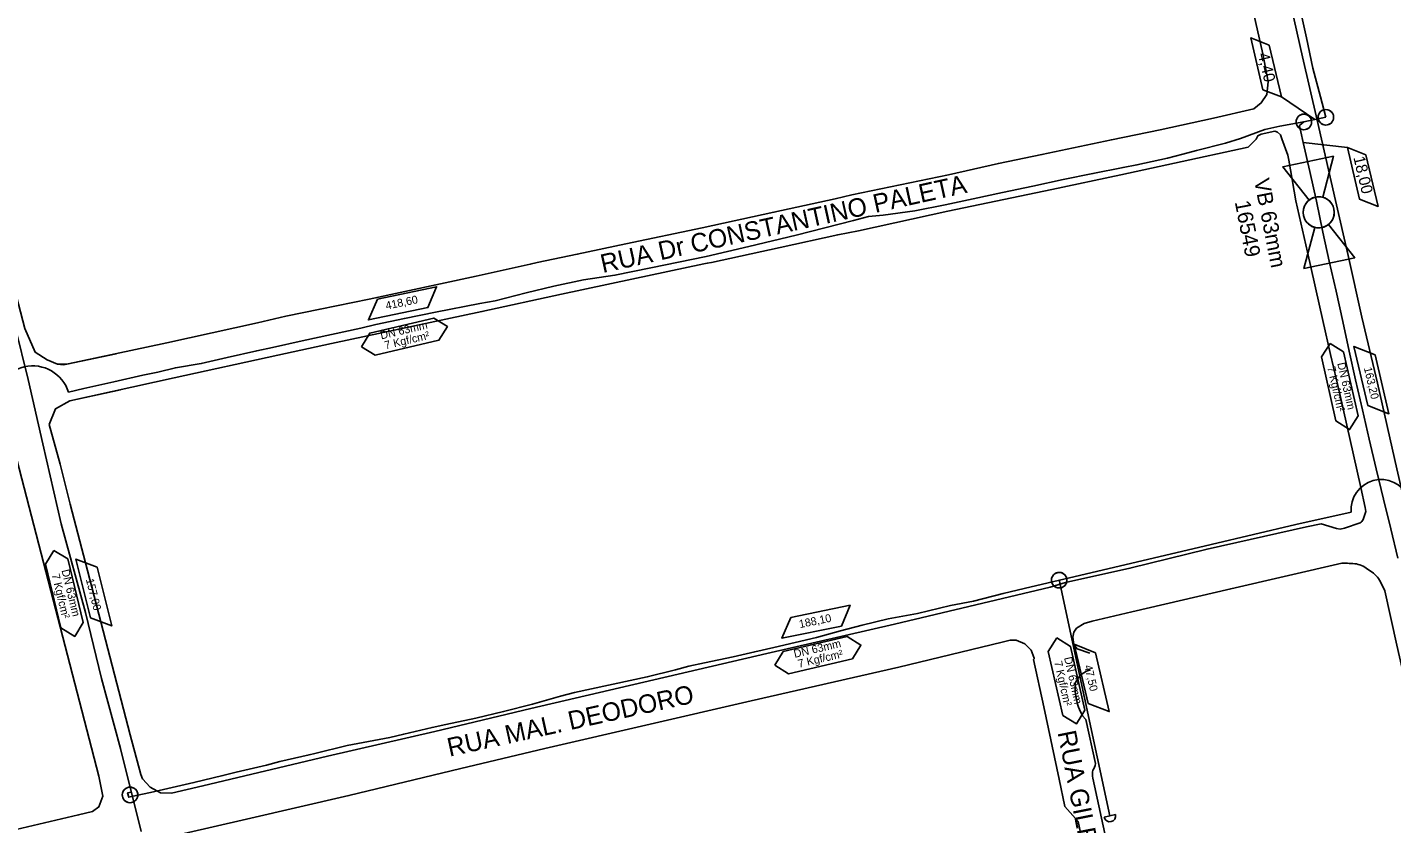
# Model space of a CAD drawing. Extents: x 656692 to 673945, y 7585994 to 7599066.
# Drawn here: x 669316 to 669847, y 7594083 to 7594394 of the extents above; entities that cross this region are included whole.
import ezdxf

# ---------------------------------------------------------------- set-up
doc = ezdxf.new("R2010")
doc.units = 0
for name, color, linetype in [('LOGRADOURO', 7, 'Continuous'), ('LOGRADOURO_TEXTO', 7, 'Continuous'), ('SIMBOLO', 7, 'Continuous'), ('TEXTO', 7, 'Continuous'), ('TUBO_PEAD_GN_63', 7, 'Continuous'), ('VALVULA_PEAD_63', 7, 'Continuous')]:
    doc.layers.add(name, color=color, linetype=linetype)

# ---------------------------------------------------------------- blocks, each defined once
blk = doc.blocks.new('VALVULA_PEAD_DN_16')
at = {"layer": 'VALVULA_PEAD_63'}
for points in [[(-0.0374, 0.0187), (-0.1395, 0.0698), (-0.1395, -0.0698), (-0.0374, -0.0187)], [(-0.0374, -0.0187), (-0.1395, -0.0698), (-0.1395, 0.0698), (-0.0374, 0.0187)], [(0.0374, -0.0187), (0.1395, -0.0698), (0.1395, 0.0698), (0.0374, 0.0187)], [(0.0374, -0.0187), (0.1395, -0.0698), (0.1395, 0.0698), (0.0374, 0.0187)]]:
    blk.add_lwpolyline(points, dxfattribs=at)
blk.add_circle((0, 0), 0.0419, dxfattribs=at)
for start, end in [(90, 270), (270, 90), (153.4349, 206.5651), (333.4349, 26.5651)]:
    blk.add_arc((0, 0), 0.0419, start, end, dxfattribs=at)
blk = doc.blocks.new('INTERLIGACAO_9')
at = {"layer": 'SIMBOLO'}
blk.add_circle((0, 0), 4.19, dxfattribs=at)
for start, end in [(0, 180), (180, 0)]:
    blk.add_arc((0, 0), 4.19, start, end, dxfattribs=at)

msp = doc.modelspace()

# ---------------------------------------------------------------- linework, layer by layer
at = {"layer": 'LOGRADOURO'}
for p, q in [((669842.27, 7594178.34), (669844.27, 7594174.24)), ((669723.74, 7594135.02), (669723.83, 7594138.2))]:
    msp.add_line(p, q, dxfattribs=at)
for points in [[(670024.2, 7594248.68), (669972.2, 7594236.37), (669931.63, 7594226.92), (669869.93, 7594210.34), (669856.39, 7594207.15), (669854.57, 7594207.25), (669852.09, 7594209.19), (669851.15, 7594212.12), (669848.91, 7594221.72), (669841.45, 7594254.98), (669835.32, 7594280.76), (669830.05, 7594304.69), (669825.15, 7594326.15), (669817.99, 7594357.4), (669812.29, 7594382.1), (669805.54, 7594412.15), (669795.17, 7594458.34), (669789.2, 7594484.52), (669783.85, 7594507.78), (669783.6, 7594509.19)], [(669791.14, 7594408.52), (669796.84, 7594383.21), (669798.93, 7594372.38), (669798.43, 7594367.46), (669796.19, 7594364.14), (669793.36, 7594361.81), (669777.61, 7594358.26), (669756.85, 7594353.7), (669737.87, 7594349.81), (669710.83, 7594344.03), (669693.95, 7594340.59), (669674.47, 7594336.18), (669636.84, 7594328.35), (669630.36, 7594326.73), (669606.58, 7594321.58), (669578.61, 7594315.53), (669548.98, 7594309.31), (669530.03, 7594305.21), (669514.48, 7594301.97), (669511.79, 7594301.3), (669490.72, 7594296.7), (669449.07, 7594287.72), (669429.99, 7594283.86), (669416.64, 7594281.05), (669405.61, 7594278.53), (669370.37, 7594270.78), (669330.2, 7594262.18), (669327.81, 7594262.48)], [(669317.17, 7594405.59), (669298.03, 7594400.79), (669290.46, 7594398.86), (669287.17, 7594397.24), (669285.24, 7594393.34), (669285.69, 7594389.46), (669291.47, 7594367.59), (669298.18, 7594341.51), (669310.16, 7594295.23), (669315.1, 7594276.26), (669319.11, 7594267.04), (669323.78, 7594264.11), (669327.81, 7594262.48), (669331.42, 7594262.39), (669350.64, 7594266.44)], [(669835.91, 7594201.96), (669836.26, 7594203.1), (669836.85, 7594205.01), (669836.65, 7594206.64), (669834.92, 7594214.44), (669826.59, 7594251.45), (669823.16, 7594266.14), (669820.12, 7594279.48), (669814.18, 7594305.97), (669809.6, 7594326.05), (669806.91, 7594341.89), (669806.55, 7594343.76), (669804.24, 7594350.16), (669803.72, 7594351.76), (669802.58, 7594352.8), (669801.53, 7594353.14), (669796.22, 7594351.98), (669794.82, 7594351.32), (669794.18, 7594350.07), (669791.16, 7594346.97), (669762.39, 7594340.67), (669741.62, 7594336.16), (669714.71, 7594330.41), (669674.22, 7594321.95), (669639.47, 7594314.27), (669631.41, 7594312.82), (669608.99, 7594307.86), (669582.28, 7594302.03), (669580.64, 7594301.72), (669579.35, 7594301.52), (669551.26, 7594295.46), (669523.89, 7594289.65), (669492.98, 7594282.9), (669434.5, 7594270.52), (669413.51, 7594265.91), (669373.18, 7594257.09), (669332.67, 7594248.2)], [(669352.29, 7594252.38), (669332.67, 7594248.2), (669327.1, 7594245.08), (669324.58, 7594238.97), (669328.84, 7594223.51), (669332.75, 7594207.95), (669339.49, 7594182.09), (669356.12, 7594118.05), (669360.23, 7594102.61), (669360.93, 7594100.95), (669363.89, 7594097.66), (669367.94, 7594095.56), (669372.14, 7594095.4), (669384.42, 7594098.21), (669432.91, 7594109.8), (669474.71, 7594119.41), (669511.95, 7594128.32), (669603.86, 7594149.78), (669653.49, 7594161.25), (669714.02, 7594175.63), (669720.03, 7594177.37), (669745.1, 7594182.97), (669775.12, 7594190.43), (669813.77, 7594199.06), (669819.48, 7594200.23), (669825.46, 7594198.43), (669826.89, 7594198.21), (669828.62, 7594198.59), (669834.65, 7594200.61)], [(669144.7, 7594073.93), (669137.37, 7594105.37), (669122.75, 7594168.91), (669118.63, 7594186.53), (669118.34, 7594190.77), (669118.83, 7594193.98), (669120.36, 7594197.58), (669122.56, 7594200.59), (669125.4, 7594202.82), (669129.58, 7594204.59), (669141.27, 7594207.14), (669198.19, 7594219.23), (669286.54, 7594238.08), (669302.61, 7594241.49), (669305.62, 7594239.87), (669308.87, 7594237.31), (669313.91, 7594217.8), (669343.96, 7594102.04), (669345.49, 7594094.21), (669343.95, 7594090.04), (669341.51, 7594088.21), (669336.03, 7594086.89), (669166.09, 7594046.95)], [(669729.44, 7594149.86), (669724.62, 7594151.64), (669723.27, 7594153.33), (669722.86, 7594156.13), (669723.23, 7594158.06), (669724.32, 7594159.68), (669727.34, 7594161.48), (669730.43, 7594162.32), (669745.85, 7594166), (669784.31, 7594174.95), (669827.58, 7594184.93)], [(669844.29, 7594174.15), (669848.99, 7594153.03), (669865.07, 7594082.65), (669877.69, 7594026.09), (669877.77, 7594023.39), (669876.85, 7594019.84), (669874.94, 7594017.07), (669870.92, 7594013.64), (669867.24, 7594012.12), (669842.96, 7594006.39), (669820.31, 7594000.97), (669808.37, 7593998.31), (669785.43, 7593992.94), (669757.11, 7593987.72), (669755.63, 7593988.6), (669754.37, 7593990.37), (669752.09, 7593995.89), (669747.5, 7594020.25), (669739.77, 7594059.28), (669730.61, 7594101.25)], [(669377.06, 7594079.74), (669401.35, 7594085.23), (669441.25, 7594094.46), (669484.82, 7594105.02), (669517.5, 7594112.76), (669597.67, 7594131.29), (669655.17, 7594144.51), (669695.33, 7594154.12), (669698.56, 7594154.95), (669700.89, 7594154.97), (669704.18, 7594153.59), (669706.73, 7594151.01), (669707.8, 7594147.99), (669707.87, 7594147.7), (669707.54, 7594147.4), (669711.63, 7594129.04), (669717.52, 7594100.78), (669719.8, 7594090.22), (669724.96, 7594084.4), (669728.09, 7594069.45)], [(669726.11, 7594141.59), (669728.26, 7594142.86), (669729.76, 7594143.37)], [(669731.67, 7594106.9), (669727.93, 7594124.01), (669726.59, 7594125.49), (669725.43, 7594127.94)]]:
    msp.add_lwpolyline(points, dxfattribs=at)
for centre, radius, start, end in [((669832.45, 7594203.93), 3.98, 303.5782, 330.2964), ((669827.73, 7594134.89), 50.04, 83.6465, 90.1765), ((669830.77, 7594173.29), 11.6, 50.5241, 77.5736), ((669831.36, 7594170.95), 13.17, 34.0996, 59.0132), ((669844.47, 7594174.24), 0.199, 179.9891, 207.9687), ((669734.48, 7594133.52), 11.63, 136.0352, 156.2491), ((669761.04, 7594140.2), 37.66, 187.9049, 198.9943), ((669747.66, 7594102.57), 17.1, 174.1011, 184.436), ((669726.3, 7594107.53), 5.4, 323.6091, 353.3635)]:
    msp.add_arc(centre, radius, start, end, dxfattribs=at)
at = {"layer": 'SIMBOLO'}
for points in [[(669446.06, 7594269.2), (669449.35, 7594274.52), (669474.22, 7594280.35), (669479.53, 7594277.05), (669476.24, 7594271.73), (669451.38, 7594265.9), (669446.06, 7594269.2)], [(669822.96, 7594270.52), (669828.26, 7594267.18), (669833.9, 7594242.28), (669830.57, 7594236.98), (669825.28, 7594240.32), (669819.63, 7594265.23), (669822.96, 7594270.52)], [(669326.45, 7594189.87), (669331.79, 7594186.61), (669337.79, 7594161.79), (669334.53, 7594156.45), (669329.19, 7594159.71), (669323.19, 7594184.53), (669326.45, 7594189.87)], [(669606.92, 7594145.21), (669610.22, 7594150.53), (669635.08, 7594156.36), (669640.4, 7594153.06), (669637.1, 7594147.75), (669612.24, 7594141.91), (669606.92, 7594145.21)], [(669716.66, 7594155.88), (669721.95, 7594152.55), (669727.6, 7594127.64), (669724.26, 7594122.35), (669718.97, 7594125.69), (669713.32, 7594150.59), (669716.66, 7594155.88)]]:
    msp.add_lwpolyline(points, dxfattribs=at)
at = {"layer": 'TEXTO'}
for p, q in [((669804.02, 7594366.52), (669817.06, 7594357.64)), ((669829.76, 7594346.78), (669812.48, 7594348.73))]:
    msp.add_line(p, q, dxfattribs=at)
for points in [[(669799.32, 7594386.57), (669804.02, 7594366.52), (669796.86, 7594369.29), (669792.13, 7594389.47), (669799.32, 7594386.57)], [(669836.95, 7594343.88), (669841.65, 7594323.84), (669834.49, 7594326.61), (669829.76, 7594346.78), (669836.95, 7594343.88)], [(669452.32, 7594287.79), (669475.34, 7594292.54), (669471.96, 7594284.46), (669448.8, 7594279.67), (669452.32, 7594287.79)], [(669452.33, 7594287.79), (669475.34, 7594292.54), (669471.96, 7594284.46), (669448.8, 7594279.67), (669452.33, 7594287.79)], [(669840.48, 7594266), (669845.85, 7594243.12), (669837.68, 7594246.28), (669832.28, 7594269.3), (669840.48, 7594266)], [(669840.48, 7594266), (669845.85, 7594243.11), (669837.68, 7594246.28), (669832.28, 7594269.3), (669840.48, 7594266)], [(669343.24, 7594183.35), (669348.93, 7594160.54), (669340.71, 7594163.59), (669334.99, 7594186.53), (669343.24, 7594183.35)], [(669613.19, 7594163.8), (669636.21, 7594168.55), (669632.83, 7594160.47), (669609.67, 7594155.68), (669613.19, 7594163.8)], [(669731.66, 7594150.04), (669737.03, 7594127.15), (669728.86, 7594130.32), (669723.46, 7594153.34), (669731.66, 7594150.04)], [(669731.66, 7594150.03), (669737.03, 7594127.15), (669728.86, 7594130.31), (669723.46, 7594153.34), (669731.66, 7594150.03)]]:
    msp.add_lwpolyline(points, dxfattribs=at)
at = {"layer": 'TUBO_PEAD_GN_63'}
for p, q in [((669717.56, 7594178.42), (669737.27, 7594086.52)), ((669735.06, 7594086.02), (669739.49, 7594087.02))]:
    msp.add_line(p, q, dxfattribs=at)
for points in [[(669808.76, 7594412.5), (669813.77, 7594389.54), (669816.31, 7594377.71), (669819.24, 7594366.52), (669821.34, 7594358.54)], [(669332.12, 7594251.52), (669338.04, 7594252.94), (669349.77, 7594255.55), (669360.98, 7594258.11), (669366.93, 7594259.34), (669373.71, 7594261), (669383.76, 7594262.66), (669393.86, 7594265.01), (669405.33, 7594267.62), (669411.48, 7594268.91), (669423.08, 7594271.48), (669434.44, 7594273.93), (669445.89, 7594276.44), (669451.66, 7594277.84), (669462.83, 7594280.25), (669474.95, 7594282.64), (669492.21, 7594286.01), (669498.11, 7594287.04), (669510.19, 7594290.19), (669520.94, 7594292.77), (669532.45, 7594295.25), (669544.73, 7594297.06), (669558.72, 7594299.95), (669580.19, 7594304.3), (669596.79, 7594308.23), (669615.18, 7594312.69), (669637.6, 7594318.32), (669643.38, 7594319.88), (669649.09, 7594320.41), (669661.36, 7594322.08), (669673.19, 7594324.49), (669684.06, 7594326.78), (669695.47, 7594329.24), (669707.3, 7594331.73), (669719.17, 7594334.29), (669730.72, 7594336.62), (669742.41, 7594339), (669747.84, 7594340.01), (669759.77, 7594342.66), (669765.72, 7594344.16), (669771.06, 7594345.62), (669782.3, 7594348.47), (669788.14, 7594350.3), (669797.53, 7594353.77), (669803.46, 7594355.08), (669812.78, 7594356.74), (669821.34, 7594358.54)], [(669812.78, 7594356.74), (669811.24, 7594355.53), (669811.04, 7594355.24), (669811.64, 7594352.88), (669812.48, 7594348.73), (669815.09, 7594337.38), (669817.66, 7594325.92), (669820.13, 7594313.87), (669822.66, 7594302.58), (669825.32, 7594290.84), (669827.98, 7594278.99), (669830.39, 7594267.53), (669832.91, 7594256.26), (669835.6, 7594244.59), (669838.2, 7594233.24), (669840.87, 7594221.62), (669843.71, 7594209.92), (669846.67, 7594198.27), (669849.35, 7594186.92)], [(669306.28, 7594297.44), (669316.4, 7594256.51), (669322.15, 7594231.35), (669329.24, 7594200.27), (669338.71, 7594165.78), (669344.89, 7594140.07), (669352.34, 7594112.8), (669360.39, 7594080.42)], [(669356.56, 7594095.82), (669355.13, 7594095.47), (669355.56, 7594093.79), (669358.44, 7594094.52), (669364.03, 7594095.65), (669380.93, 7594099.48), (669392.21, 7594102.22), (669397.4, 7594103.62), (669409.21, 7594106.32), (669414.4, 7594107.67), (669425.71, 7594110.32), (669427.91, 7594110.82), (669440.53, 7594113.94), (669457.14, 7594117.1), (669462.58, 7594118.42), (669473.61, 7594120.97), (669478.98, 7594122.14), (669490.56, 7594124.57), (669501.39, 7594127.15), (669512.65, 7594130.05), (669523.58, 7594133.11), (669529.01, 7594134.61), (669557.32, 7594140.62), (669568.26, 7594143.46), (669573.48, 7594144.81), (669579.61, 7594146.16), (669590.7, 7594148.53), (669599.12, 7594150.46), (669606.53, 7594152.08), (669623.09, 7594155.94), (669632.55, 7594158.54), (669640.98, 7594160.74), (669651.02, 7594163.21), (669662.44, 7594165.32), (669675.26, 7594168.41), (669684.24, 7594170.2), (669695.77, 7594173.17), (669706.71, 7594175.76), (669734.36, 7594182.26), (669776.72, 7594192.24), (669809.67, 7594199.96), (669831.24, 7594204.74)]]:
    msp.add_lwpolyline(points, dxfattribs=at)
for centre, radius, start, end in [((669318.15, 7594247.12), 14.64, 17.4776, 188.0781), ((669842.81, 7594205.88), 11.63, 24.5139, 185.6005), ((669737.27, 7594086.52), 2.27, 192.7108, 12.7108)]:
    msp.add_arc(centre, radius, start, end, dxfattribs=at)

# ---------------------------------------------------------------- block references
at = {"layer": 'SIMBOLO', "xscale": 0.7229249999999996, "yscale": 0.7229249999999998, "rotation": 166.312122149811}
for p in [(669812.78, 7594356.74), (669821.34, 7594358.54), (669717.58, 7594178.32), (669356.07, 7594094.71)]:
    msp.add_blockref('INTERLIGACAO_9', p, dxfattribs=at)
at = {"layer": 'VALVULA_PEAD_63', "xscale": 144.5849999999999, "yscale": 144.58499999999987, "rotation": -78.18143432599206}
msp.add_blockref('VALVULA_PEAD_DN_16', (669818.56, 7594321.54), dxfattribs=at)

# ---------------------------------------------------------------- texts
for s, p in [('VB 63mm', (669793.36, 7594334.11)), ('16549', (669785.87, 7594325.58))]:
    msp.add_text(s, height=6, rotation=281.048).set_placement(p)
at = {"layer": 'LOGRADOURO_TEXTO'}
for s, rotation, p in [('RUA Dr CONSTANTINO PALETA', 12.4426, (669539.98, 7594297.89)), ('RUA MAL. DEODORO', 12.4426, (669480.34, 7594109.57)), ('RUA GILBERTO DE ALENCAR', 281.2052, (669716.89, 7594119.08))]:
    msp.add_text(s, height=7.2, rotation=rotation, dxfattribs=at).set_placement(p)
at = {"layer": 'TEXTO'}
for s, height, rotation, p in [('4,40', 4.447, 283.1976, (669794.86, 7594383.17)), ('18,00', 4.447, 283.1976, (669832.03, 7594342.88)), ('418,60', 3.113, 11.6706, (669455.81, 7594283.63)), ('DN 63mm', 3.113, 13.1976, (669453.82, 7594272.05)), ('7 Kgf/cm²', 3.113, 13.1976, (669455.47, 7594268.2)), ('DN 63mm', 3.113, 282.775, (669825.76, 7594262.73)), ('7 Kgf/cm²', 3.113, 282.775, (669821.9, 7594261.11)), ('163,20', 3.113, 283.1976, (669836.11, 7594260.91)), ('7 Kgf/cm²', 3.113, 283.5974, (669325.52, 7594180.45)), ('DN 63mm', 3.113, 283.5974, (669329.36, 7594182.13)), ('157,00', 3.113, 284.0201, (669338.84, 7594178.59)), ('188,10', 3.113, 11.6706, (669616.68, 7594159.64)), ('DN 63mm', 3.113, 13.1976, (669614.68, 7594148.06)), ('7 Kgf/cm²', 3.113, 13.1976, (669616.33, 7594144.21)), ('7 Kgf/cm²', 3.113, 282.775, (669715.59, 7594146.48)), ('DN 63mm', 3.113, 282.775, (669719.46, 7594148.1)), ('47,50', 3.113, 283.1976, (669727.29, 7594144.95))]:
    msp.add_text(s, height=height, rotation=rotation, dxfattribs=at).set_placement(p)

doc.saveas('drawing.dxf')
